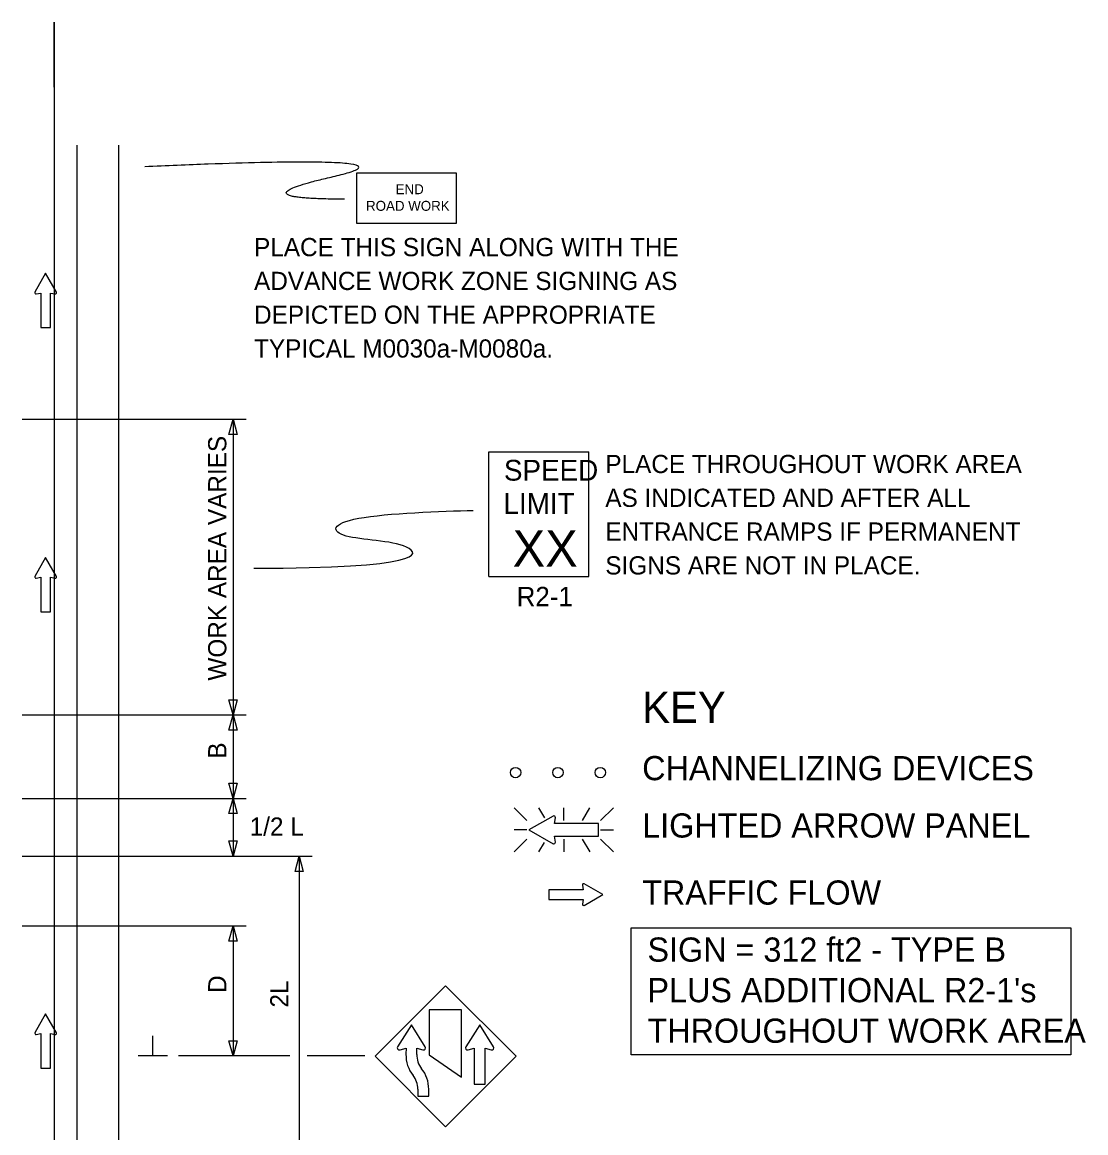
# Model space of a CAD drawing. Extents: x 16450 to 18482, y 7002 to 8333.
# Drawn here: x 17007.6 to 17416.6, y 7831.7 to 8258.9 of the extents above; entities that cross this region are included whole.
import ezdxf

# ---------------------------------------------------------------- set-up
doc = ezdxf.new("R2010")
doc.units = 0
for name, color, linetype in [('ALI_LEGAL_EX', 7, 'Continuous'), ('MT_SCRATCH_LEVEL_E', 7, 'Continuous'), ('PAVT_EDGE_EX', 7, 'Continuous'), ('TRAFFIC_SIGNS_PR', 7, 'Continuous'), ('TYPICAL_TEXT_DIMEN_EX', 7, 'Continuous'), ('TYPICAL_TEXT_DIMEN_PR', 7, 'Continuous')]:
    doc.layers.add(name, color=color, linetype=linetype)

msp = doc.modelspace()

# ---------------------------------------------------------------- linework, layer by layer
at = {"layer": 'ALI_LEGAL_EX'}
msp.add_line((17019.95, 8258.85), (17019.95, 7440.72), dxfattribs=at)
msp.add_lwpolyline([(17019.95, 8233.85), (17019.95, 8258.85)], dxfattribs=at)
at = {"layer": 'MT_SCRATCH_LEVEL_E'}
for p, q in [((17016.63, 8162.31), (17012.52, 8155.07)), ((17020.78, 8155.07), (17016.63, 8162.31)), ((17013, 8154.39), (17014.78, 8154.7)), ((17014.78, 8154.7), (17014.78, 8141.44)), ((17018.52, 8141.44), (17018.52, 8154.7)), ((17018.52, 8154.7), (17020.3, 8154.39)), ((17014.78, 8141.44), (17018.52, 8141.44)), ((17016.63, 8052.96), (17012.52, 8045.72)), ((17020.78, 8045.72), (17016.63, 8052.96)), ((17013, 8045.03), (17014.78, 8045.35)), ((17014.78, 8045.35), (17014.78, 8032.09)), ((17018.52, 8032.09), (17018.52, 8045.35)), ((17018.52, 8045.35), (17020.3, 8045.03)), ((17014.78, 8032.09), (17018.52, 8032.09)), ((17223.36, 7925.18), (17210.1, 7925.18)), ((17210.1, 7925.18), (17210.1, 7921.44)), ((17223.05, 7926.96), (17223.36, 7925.18)), ((17230.97, 7923.33), (17223.73, 7927.44)), ((17210.1, 7921.44), (17223.36, 7921.44)), ((17223.36, 7921.44), (17223.05, 7919.66)), ((17223.73, 7919.18), (17230.97, 7923.33)), ((17016.63, 7877.45), (17012.52, 7870.21)), ((17020.78, 7870.21), (17016.63, 7877.45)), ((17013, 7869.53), (17014.78, 7869.84)), ((17014.78, 7869.84), (17014.78, 7856.59)), ((17018.52, 7856.59), (17018.52, 7869.84)), ((17018.52, 7869.84), (17020.3, 7869.53)), ((17014.78, 7856.59), (17018.52, 7856.59))]:
    msp.add_line(p, q, dxfattribs=at)
for centre, start, end in [((17012.93, 8154.84), 150.4248, 279.9638), ((17020.37, 8154.85), 260.0362, 29.7731), ((17012.93, 8045.49), 150.4248, 279.9638), ((17020.37, 8045.49), 260.0362, 29.7731), ((17223.5, 7927.03), 60.4248, 189.9638), ((17223.51, 7919.59), 170.0362, 299.7731), ((17012.93, 7869.99), 150.4248, 279.9638), ((17020.37, 7869.99), 260.0362, 29.7731)]:
    msp.add_arc(centre, 0.463, start, end, dxfattribs=at)
at = {"layer": 'PAVT_EDGE_EX'}
for p, q in [((17028.68, 8211.52), (17028.68, 7562.44)), ((17044.68, 8211.52), (17044.68, 7562.44))]:
    msp.add_line(p, q, dxfattribs=at)
at = {"layer": 'TRAFFIC_SIGNS_PR'}
for p, q in [((17187.1, 8093.67), (17225.5, 8093.67)), ((17187.1, 8045.67), (17187.1, 8093.67)), ((17225.5, 8045.67), (17225.5, 8093.67)), ((17187.1, 8045.67), (17225.5, 8045.67)), ((17196.78, 7956.71), (17201.72, 7951.78)), ((17208.54, 7952.89), (17206.34, 7956.72)), ((17215.86, 7951.78), (17215.86, 7956.72)), ((17223.1, 7951.78), (17225.95, 7956.72)), ((17230.01, 7951.78), (17234.95, 7956.72)), ((17201.72, 7948.23), (17196.78, 7948.23)), ((17230.01, 7948.23), (17234.95, 7948.23)), ((17196.78, 7939.74), (17201.72, 7944.67)), ((17206.29, 7939.74), (17208.41, 7943.4)), ((17215.86, 7944.67), (17215.86, 7939.74)), ((17225.99, 7939.74), (17223.14, 7944.67)), ((17230.01, 7944.67), (17234.95, 7939.73)), ((17170.44, 7888.27), (17143.29, 7861.11)), ((17197.6, 7861.11), (17170.44, 7888.27)), ((17143.29, 7861.11), (17170.44, 7833.96)), ((17170.44, 7833.96), (17197.6, 7861.11))]:
    msp.add_line(p, q, dxfattribs=at)
for points in [[(17136.23, 8181.57), (17174.63, 8181.57), (17174.63, 8200.77), (17136.23, 8200.77)], [(17164.13, 7879.05), (17164.13, 7861.7), (17176.54, 7853.08), (17176.54, 7879.05)]]:
    msp.add_lwpolyline(points, close=True, dxfattribs=at)
for points in [[(17211.79, 7953.5), (17202.5, 7948.23), (17211.79, 7942.9)], [(17212.67, 7943.53), (17212.27, 7945.8), (17229.28, 7945.8), (17229.28, 7950.6), (17212.27, 7950.6), (17212.67, 7952.88)], [(17162.64, 7864.82), (17157.31, 7873.19), (17151.98, 7864.82)], [(17188.86, 7864.82), (17183.54, 7873.19), (17178.21, 7864.82)], [(17152.91, 7863.56), (17155.21, 7864.19), (17155.2, 7861.96)], [(17159.4, 7861.85), (17159.4, 7864.19), (17161.7, 7863.56)], [(17179.14, 7863.56), (17181.44, 7864.19), (17181.44, 7850.39), (17185.64, 7850.39), (17185.64, 7864.19), (17187.93, 7863.56)], [(17159.77, 7848.5), (17159.77, 7845.85), (17163.97, 7845.85), (17163.97, 7848.5)]]:
    msp.add_lwpolyline(points, dxfattribs=at)
for centre in [(17197.34, 7970.26), (17213.64, 7970.26), (17229.94, 7970.26)]:
    msp.add_circle(centre, 2, dxfattribs=at)
for centre, radius, start, end in [((17212.08, 7952.98), 0.598, 350.7308, 118.8916), ((17212.08, 7943.43), 0.597, 241.4833, 9.9593), ((17152.69, 7864.37), 0.84, 147.5204, 285.3986), ((17161.93, 7864.37), 0.842, 254.6828, 32.2708), ((17171.49, 7870.45), 10.5, 212.4569, 212.4665), ((17178.92, 7864.37), 0.841, 147.5497, 285.3316), ((17188.15, 7864.37), 0.839, 254.6778, 32.4665), ((17197.72, 7870.45), 10.5, 212.4569, 212.4665), ((17167.79, 7861.59), 12.59, 178.3293, 218.5427), ((17148.9, 7862.19), 10.5, 358.1894, 0.0048), ((17167.79, 7861.59), 8.4, 178.1936, 218.5465), ((17158.93, 7853.43), 10.5, 74.68, 74.6808), ((17151.37, 7848.5), 12.6, 0, 38.5422), ((17151.37, 7848.5), 8.4, 0, 38.5457)]:
    msp.add_arc(centre, radius, start, end, dxfattribs=at)
msp.add_open_spline([(17131.52, 8190.8), (17089.01, 8190.8), (17165.53, 8208.21), (17054.74, 8203.27)], degree=2, dxfattribs=at)
at = {"layer": 'TYPICAL_TEXT_DIMEN_EX'}
msp.add_lwpolyline([(17241.85, 7910.49), (17410.86, 7910.49), (17410.86, 7861.66), (17241.85, 7861.66)], close=True, dxfattribs=at)
at = {"layer": 'TYPICAL_TEXT_DIMEN_PR'}
for p, q in [((17007.61, 8106.12), (17093.68, 8106.12)), ((17087.11, 8100.26), (17088.68, 8106.12)), ((17088.68, 8106.12), (17088.68, 7992.4)), ((17088.68, 8106.12), (17090.25, 8100.26)), ((17088.68, 8100.26), (17087.11, 8100.26)), ((17090.25, 8100.26), (17088.68, 8100.26)), ((17088.68, 7992.4), (17087.11, 7998.26)), ((17087.11, 7998.26), (17088.68, 7998.26)), ((17088.68, 7998.26), (17090.25, 7998.26)), ((17090.25, 7998.26), (17088.68, 7992.4)), ((17007.61, 7992.4), (17093.68, 7992.4)), ((17087.11, 7986.54), (17088.68, 7992.4)), ((17088.68, 7992.4), (17088.68, 7960.32)), ((17088.68, 7992.4), (17090.25, 7986.54)), ((17088.68, 7986.54), (17087.11, 7986.54)), ((17090.25, 7986.54), (17088.68, 7986.54)), ((17088.68, 7967.41), (17088.68, 7963.82)), ((17088.68, 7960.32), (17087.11, 7966.18)), ((17087.11, 7966.18), (17088.68, 7966.18)), ((17088.68, 7966.18), (17090.25, 7966.18)), ((17090.25, 7966.18), (17088.68, 7960.32)), ((17007.61, 7960.32), (17093.68, 7960.32)), ((17087.11, 7954.46), (17088.68, 7960.32)), ((17088.68, 7960.32), (17088.68, 7938.07)), ((17088.68, 7960.32), (17090.25, 7954.46)), ((17088.68, 7954.46), (17087.11, 7954.46)), ((17090.25, 7954.46), (17088.68, 7954.46)), ((17088.68, 7938.07), (17087.11, 7943.94)), ((17087.11, 7943.94), (17088.68, 7943.94)), ((17088.68, 7943.94), (17090.25, 7943.94)), ((17090.25, 7943.94), (17088.68, 7938.07)), ((17007.61, 7938.07), (17119.11, 7938.07)), ((17112.54, 7932.21), (17114.11, 7938.07)), ((17114.11, 7938.07), (17114.11, 7820.2)), ((17114.11, 7938.07), (17115.68, 7932.21)), ((17114.11, 7932.21), (17112.54, 7932.21)), ((17115.68, 7932.21), (17114.11, 7932.21)), ((17007.61, 7911.27), (17093.68, 7911.27)), ((17087.11, 7905.41), (17088.68, 7911.27)), ((17088.68, 7911.27), (17088.68, 7861.27)), ((17088.68, 7911.27), (17090.25, 7905.41)), ((17088.68, 7905.41), (17087.11, 7905.41)), ((17090.25, 7905.41), (17088.68, 7905.41)), ((17057.8, 7861.27), (17057.8, 7869.05)), ((17088.68, 7861.27), (17087.11, 7867.13)), ((17087.11, 7867.13), (17088.68, 7867.13)), ((17088.68, 7867.13), (17090.25, 7867.13)), ((17090.25, 7867.13), (17088.68, 7861.27)), ((17063.43, 7861.27), (17052.18, 7861.27)), ((17110.51, 7861.27), (17067.68, 7861.27)), ((17139.34, 7861.27), (17117.17, 7861.27))]:
    msp.add_line(p, q, dxfattribs=at)
for points, degree in [([(17096.66, 8048.87), (17161.24, 8048.87), (17161.24, 8059.63), (17126.33, 8059.63), (17126.33, 8069.29), (17169.19, 8070.81), (17181.1, 8071.07)], 3), ([(17206.24, 8042.65), (17206.25, 8042.65), (17206.26, 8042.65), (17206.26, 8042.65)], 2)]:
    msp.add_open_spline(points, degree=degree, dxfattribs=at)

# ---------------------------------------------------------------- texts
at = {"layer": 'TRAFFIC_SIGNS_PR'}
for s, height, p in [('END', 3.831, (17151.24, 8192.7)), ('ROAD WORK', 3.831, (17139.84, 8186.31)), ('PLACE THIS SIGN ALONG WITH THE', 7, (17096.77, 8168.86)), ('ADVANCE WORK ZONE SIGNING AS', 7, (17096.77, 8155.86)), ('DEPICTED ON THE APPROPRIATE', 7, (17096.77, 8142.86)), ('TYPICAL M0030a-M0080a.', 7, (17096.77, 8129.86)), ('SPEED', 8, (17192.87, 8082.53)), ('PLACE THROUGHOUT WORK AREA', 7, (17231.86, 8085.44)), ('LIMIT', 8, (17192.71, 8069.73)), ('AS INDICATED AND AFTER ALL', 7, (17231.86, 8072.44)), ('ENTRANCE RAMPS IF PERMANENT', 7, (17231.86, 8059.44)), ('XX', 14.031, (17196.21, 8049.43)), ('SIGNS ARE NOT IN PLACE.', 7, (17231.86, 8046.44)), ('R2-1', 7.44, (17197.78, 8034.23))]:
    msp.add_text(s, height=height, dxfattribs=at).set_placement(p)
at = {"layer": 'TYPICAL_TEXT_DIMEN_EX'}
for s, height, p in [('KEY', 12, (17246.04, 7989.36)), ('CHANNELIZING DEVICES', 9.3, (17246.04, 7967.31)), ('LIGHTED ARROW PANEL', 9.3, (17246.04, 7945.26)), ('TRAFFIC FLOW', 9.3, (17246.04, 7919.46)), ('SIGN = 312 ft2 - TYPE B', 9.3, (17248.08, 7897.52)), ("PLUS ADDITIONAL R2-1's", 9.3, (17248.08, 7881.92)), ('THROUGHOUT WORK AREA', 9.3, (17248.08, 7866.32))]:
    msp.add_text(s, height=height, dxfattribs=at).set_placement(p)
at = {"layer": 'TYPICAL_TEXT_DIMEN_PR'}
for s, p in [('WORK AREA VARIES', (17086.12, 8005.62)), ('B', (17086.12, 7975.59)), ('D', (17086.12, 7885.49)), ('2L', (17109.98, 7879.86))]:
    msp.add_text(s, height=7, rotation=90, dxfattribs=at).set_placement(p)
msp.add_text('1/2 L', height=7, dxfattribs=at).set_placement((17095.08, 7945.99))

doc.saveas('drawing.dxf')
